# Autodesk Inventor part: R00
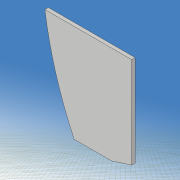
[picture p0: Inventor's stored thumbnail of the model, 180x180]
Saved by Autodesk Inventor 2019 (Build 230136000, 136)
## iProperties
Created: 2021-05
Part Number: R00
Material: 一般
Document SubType Name: Modeling
Designer: kikut
Density: 1 g/cm^3
Appearance: 既定
Author: kikut
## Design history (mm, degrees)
sketch "スケッチ1"
  geometry: L1 (80, 60)-(-80, 60); L2 (-80, 60)-(-80, -60); L3 (-80, -60)-(80, -60); L4 (80, -60)-(80, 60); L5 (80, 60)-(-80, -60); L6 (-80, 60)-(80, -60); 1 further point
  constraints: 12 end point, 2 midpoint, 2 parallel, 1 horizontal, 1 perpendicular
  dimensions: "d0" = 160 distance of L2.end L3.end; "d1" = 120 distance of L1.end L2.end
extrude "押し出し1" new body sketch "スケッチ1" stored distance "d2" = 0.6; taper "d3" = 0 deg
sketch "スケッチ2"
  geometry: L1 (-140, 0)-(140, 0) reference; L2 (0, -54)-(20, -30); L3 (0, 54)-(20, 30); L4 (0, -3)-(6.514, -3); L5 (6.514, -3)-(16, -6); L6 (16, -6)-(24, -3); L7 (24, -3)-(33.716, -3); L8 (0, 3)-(6.514, 3); L9 (6.514, 3)-(16, 6); L10 (16, 6)-(24, 3); L11 (24, 3)-(33.716, 3); L12 (0, -98)-(0, 98) reference; L13 (-100, -70)-(100, -70); L14 (100, -70)-(100, 70); L15 (100, 70)-(-100, 70); L16 (-100, 70)-(-100, -70); L17 (-100, -70)-(100, 70); L18 (100, -70)-(-100, 70); A1 r 60 centre (54.312, 28.5) between (0, 54) and (0, 3); A2 r 60 centre (54.312, -28.5) between (0, -3) and (0, -54); A3 r 18.111 centre (18, -12) between (20, -30) and (33.716, -3); A4 r 18.111 centre (18, 12) between (33.716, 3) and (20, 30); 1 further point
  constraints: 32 end point, 8 point on circle, 8 symmetric about line, 4 centre point, 3 horizontal, 2 collinear, 2 midpoint, 2 parallel, 1 perpendicular
  dimensions: "d5" = 60 radius of A1; "d6" = 6 distance of L8.start L4.start; "d7" = 108 distance of L3.start L2.start; "d8" = 0 horizontal distance of L3.start L8.start; "d9" = 60 distance of L3.end L2.end; "d10" = 0 horizontal distance of point (0, 0) L3.start; "d11" = 20 horizontal distance of L3.start L3.end; "d12" = 24 distance of A4.centre A3.centre; "d13" = 6 distance of L11.end L7.end; "d14" = 12 distance of L9.end L5.end; "d15" = 16 distance from line of L12 L5.end; "d16" = 24 distance from line of L6.end L12; "d17" = 200 distance of L14.end L15.end; "d18" = 140 distance of L15.end L13.start; "d30" = 18 distance from line of L12 A4.centre
extrude "押し出し2" cut sketch "スケッチ2" stored distance "d19" = 10; taper "d20" = 0 deg
sketch "スケッチ3"
  geometry: L1 (49.705, -17.97)-(33.948, -15.191); L2 (33.948, -15.191)-(34.295, -13.222); L3 (34.295, -13.222)-(50.052, -16); L4 (50.052, -16)-(49.705, -17.97); L5 (49.705, -17.97)-(34.295, -13.222); L6 (33.948, -15.191)-(50.052, -16); L7 (50.052, 16)-(34.295, 13.222); L8 (34.295, 13.222)-(33.948, 15.191); L9 (33.948, 15.191)-(49.705, 17.97); L10 (49.705, 17.97)-(50.052, 16); L11 (50.052, 16)-(33.948, 15.191); L12 (34.295, 13.222)-(49.705, 17.97); L13 (-112, 0)-(112, 0) reference; L14 (0, -84)-(0, 84) reference; 3 further points
  constraints: 24 end point, 4 midpoint, 4 parallel, 2 perpendicular, 2 symmetric about line
  dimensions: "d21" = 2 distance of L3.end L1.start; "d22" = 2 distance of L9.end L7.start; "d23" = 16 distance of L8.end L9.end; "d24" = 42 distance from line of L14 point (42, 15.596); "d26" = 10 deg angle of L7 L13; "d62" = 16 distance from line of L3.end L13
extrude "押し出し3" join sketch "スケッチ3" distance "d27" = 0.6; taper "d28" = 0 deg
fillet "フィレット1" dims "d31" = 2
fillet "フィレット2" dims "d32" = 1
sketch "スケッチ6"
  geometry: L1 (-20, 60)-(80, 60); L2 (80, 60)-(80, -60); L3 (80, -60)-(-20, -60); L4 (-20, -60)-(-20, 60); L5 (-46.168, 0)-(93.832, 0) reference; L6 (0, -84)-(0, 84) reference; L7 (-10, 0)-(10, 0); L8 (10, 0)-(10, 20); L9 (10, 20)-(-10, 20); L10 (-10, 20)-(-10, 0); 1 further point
  constraints: 16 end point, 4 parallel, 2 horizontal, 2 perpendicular, 1 other
  dimensions: "d63" = 120 distance of L3.end L1.start; "d64" = 100 distance of L1.start L1.end; "d65" = 20 distance between parallel lines of L6 L4; "d66" = 20 distance of L8.end L9.end; "d67" = 0 distance between parallel lines of L5 L7; "d68" = 20 distance of L9.end L7.start; "d69" = 10 distance between parallel lines of L6 L10
extrude "押し出し4" cut sketch "スケッチ6" stored distance "d70" = 10; taper "d71" = 0 deg
node "ソリッド1"
